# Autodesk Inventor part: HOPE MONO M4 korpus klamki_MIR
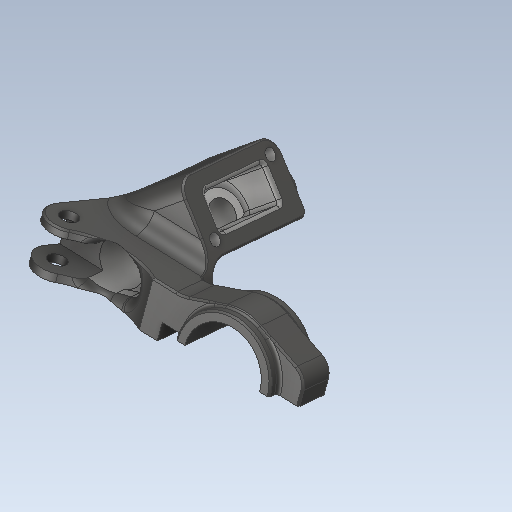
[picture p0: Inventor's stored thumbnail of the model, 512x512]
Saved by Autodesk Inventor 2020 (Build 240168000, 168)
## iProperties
Created: 2015-11
Part Number: HOPE MONO M4 korpus klamki_MIR
Material: Ogólny
Document SubType Name: Modeling
Designer: Tomasz
Density: 1 g/cm^3
Appearance: Domyślna
Sending System: SolidWorks 2017
Last Author: Tomasz
Last Saved: 2017-10-01
Author: Tomasz
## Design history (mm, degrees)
feature "Imported1"
node "Bryła1"
